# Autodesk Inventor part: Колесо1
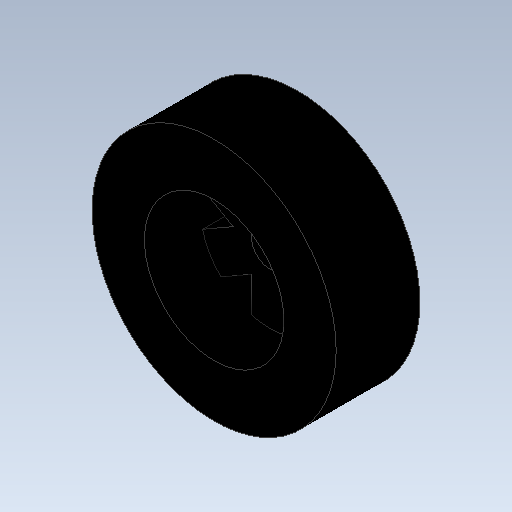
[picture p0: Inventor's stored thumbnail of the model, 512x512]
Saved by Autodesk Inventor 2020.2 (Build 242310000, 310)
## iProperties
Created: 2020-04
Part Number: Колесо1
Material: Типовые
Document SubType Name: Modeling
Designer: Алексей
Density: 1 g/cm^3
Appearance: По умолчанию
Author: Алексей
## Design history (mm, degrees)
sketch "Эскиз1"
  geometry: L1 (25.439, 33.215)-(-5.561, -20.479) reference; L2 (9.842, 9.484)-(26.543, -0.158); L3 (26.543, -0.158)-(23.893, -4.748); L4 (23.893, -4.748)-(7.192, 4.894); L5 (14.217, -7.275)-(14.217, 12.01); L6 (19.517, 12.01)-(19.517, -7.275); L7 (7.192, -0.158)-(23.893, 9.484); L8 (26.543, 4.894)-(9.842, -4.748); L9 (9.842, 9.484)-(26.543, -0.158); L10 (23.893, -4.748)-(7.192, 4.894); L11 (19.517, 12.01)-(19.517, -7.275); L12 (14.217, -7.275)-(14.217, 12.01); L13 (26.543, 4.894)-(9.842, -4.748); L14 (7.192, -0.158)-(23.893, 9.484); C1 r 17.5 at (16.867, 2.368); C2 r 10 at (16.867, 2.368); C3 r 10 at (16.867, 2.368); C4 r 10 at (16.867, 2.368); C5 r 10 at (16.867, 2.368); C6 r 10 at (16.867, 2.368); C7 r 2.65 at (16.867, 2.368); A1 r 10 centre (16.867, 2.368) between (14.217, 12.01) and (19.517, 12.01); 27 further points
  constraints: 26 end point, 8 centre point, 4 coincident, 4 point on circle, 2 tangent, 1 midpoint, 1 parallel, 51 other
  dimensions: "d0" = 35 diameter of C1; "d1" = 20 diameter of A1; "d4" = 360 deg dimension on A1.centre L3.end (derived); "d16" = 5.3 diameter of C7
extrude "Выдавливание1" new body sketch "Эскиз1" distance "d6" = 4; taper "d7" = 0 deg
sketch "Эскиз2"
  geometry: C1 r 17.5 at (0, 0); C2 r 10 at (0, 0); 1 further point
  constraints: 2 centre point, 1 coincident
  dimensions: "d9" = 35 diameter of C1; "d10" = 20 diameter of C2
extrude "Выдавливание2" join sketch "Эскиз2" distance "d11" = 8; taper "d12" = 0 deg
sketch "Эскиз3"
  geometry: C1 r 2.65 at (16.867, 2.368) reference; C2 r 5 at (16.867, 2.368); 1 further point
  constraints: 1 centre point, 1 coincident
  dimensions: "d13" = 10 diameter of C2
extrude "Выдавливание3" join sketch "Эскиз3" distance "d14" = 4; taper "d15" = 0 deg
node "Твердое тело1"
node "Ссылка1"
